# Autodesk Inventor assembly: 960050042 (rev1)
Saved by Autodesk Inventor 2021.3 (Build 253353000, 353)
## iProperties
Created: 2023-03
Part Number: 960050042 (rev1)
Document SubType Name: Assembly
Designer: AdminForWorker
Title: 960050042 (rev1) v2
Author: AdminForWorker
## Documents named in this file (2)
- z:\worker\convert-fusion-r08-cosv3\tmp\job-1\3553\output\files\82b4d9ad-b575-4129-b9ca-4964d6b72adf\960050042 (rev1) v2_5.iam
- z:\worker\convert-fusion-r08-cosv3\tmp\job-1\3553\output\files\82b4d9ad-b575-4129-b9ca-4964d6b72adf\960050042 (rev1).ipt
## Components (1 placed, 1 different names)
1. 960050042 (rev1):1
